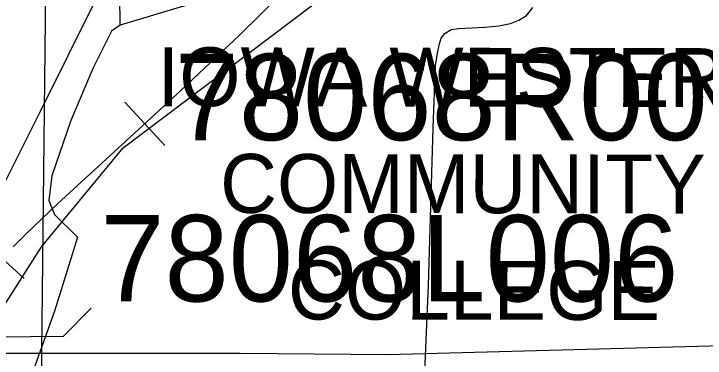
# Model space of a CAD drawing. Extents: x -132.8 to -73.3, y -60 to -26.
# Drawn here: x -119.898 to -119.017, y -48.069 to -47.631 of the extents above; entities that cross this region are included whole.
import ezdxf

# ---------------------------------------------------------------- set-up
doc = ezdxf.new("R2010")
doc.units = 0
for name, color, linetype in [('tdCoCityStreetMajor', 7, 'Continuous'), ('tdCoCityStreetMinor', 7, 'Continuous'), ('tdCoHydroRiver', 7, 'Continuous'), ('tdCoInstTxt', 7, 'Continuous'), ('tdCoPriDiv', 7, 'Continuous'), ('tdCoRRCL', 7, 'Continuous'), ('tdCoSectLine', 7, 'Continuous'), ('tdCoStrucDivPri', 7, 'Continuous'), ('tdCoStrucPriMaintName', 7, 'Continuous')]:
    doc.layers.add(name, color=color, linetype=linetype)

msp = doc.modelspace()

# ---------------------------------------------------------------- linework, layer by layer
at = {"layer": 'tdCoCityStreetMajor'}
msp.add_lwpolyline([(-119.9174, -47.86069), (-119.86389, -47.75489), (-119.79286, -47.61186)], dxfattribs=at)
at = {"layer": 'tdCoCityStreetMinor'}
msp.add_lwpolyline([(-119.37442, -48.08677), (-119.36955, -47.97618), (-119.36364, -47.77618), (-119.36068, -47.69677), (-119.35796, -47.68074), (-119.35574, -47.66915), (-119.35328, -47.66175), (-119.34859, -47.65584), (-119.3407, -47.6509), (-119.33133, -47.64967), (-119.29779, -47.6477), (-119.27979, -47.64597), (-119.26524, -47.64301), (-119.25463, -47.63882), (-119.24477, -47.6329), (-119.23663, -47.62254)], dxfattribs=at)
at = {"layer": 'tdCoHydroRiver'}
for points in [[(-119.17977, -47.29833), (-119.2348, -47.34891), (-119.2579, -47.38615), (-119.28466, -47.44222), (-119.30043, -47.50017), (-119.30089, -47.51751), (-119.31585, -47.5455), (-119.33537, -47.56707), (-119.43131, -47.61338), (-119.4646, -47.61879), (-119.51823, -47.61734), (-119.60264, -47.58666), (-119.61683, -47.58628), (-119.64432, -47.61078), (-119.68567, -47.62228), (-119.76205, -47.64545)], [(-119.76205, -47.64545), (-119.76261, -47.60758)], [(-119.76205, -47.64545), (-119.77331, -47.65304), (-119.79666, -47.69974), (-119.8253, -47.7668), (-119.84929, -47.83715), (-119.85329, -47.8686), (-119.84587, -47.88615), (-119.81667, -47.91534), (-119.82357, -47.93724), (-119.84603, -48.00921), (-119.94498, -48.2842), (-119.94822, -48.28727), (-119.96053, -48.33427), (-119.96705, -48.34198)]]:
    msp.add_lwpolyline(points, dxfattribs=at)
at = {"layer": 'tdCoPriDiv'}
msp.add_lwpolyline([(-120.61573, -48.05639), (-120.53523, -48.05674), (-120.45109, -48.06043), (-120.28612, -48.0624), (-120.14217, -48.0621), (-119.91258, -48.06262), (-119.60963, -48.06303), (-119.42124, -48.06473), (-119.01066, -48.05333), (-118.91558, -48.05033)], dxfattribs=at)
at = {"layer": 'tdCoRRCL'}
for p, q in [((-119.75624, -47.74313), (-119.70547, -47.79833)), ((-119.94025, -47.91742), (-119.8845, -47.96759)), ((-119.98769, -48.12372), (-119.86233, -47.9275))]:
    msp.add_line(p, q, dxfattribs=at)
for points in [[(-119.86233, -47.9275), (-119.75834, -47.80157), (-119.3286, -47.47698)], [(-119.89875, -47.92738), (-119.88303, -47.91165), (-119.84187, -47.87285), (-119.74443, -47.78322), (-119.68485, -47.72841), (-119.6104, -47.65803), (-119.5564, -47.60455)], [(-119.5564, -47.60455), (-119.6104, -47.65803), (-119.68485, -47.72841), (-119.74443, -47.78322), (-119.84187, -47.87285), (-119.88303, -47.91165), (-119.89875, -47.92738)]]:
    msp.add_lwpolyline(points, dxfattribs=at)
at = {"layer": 'tdCoSectLine'}
msp.add_lwpolyline([(-119.86522, -48.3731), (-119.86524, -48.36906), (-119.85445, -47.36885)], dxfattribs=at)
at = {"layer": 'tdCoStrucDivPri'}
for p, q in [((-119.83448, -48.0413), (-119.79908, -48.00541)), ((-119.93961, -48.04204), (-119.83448, -48.0413))]:
    msp.add_line(p, q, dxfattribs=at)

# ---------------------------------------------------------------- texts
at = {"layer": 'tdCoInstTxt'}
for s, p in [('IOWA WESTERN', (-119.71485, -47.74843)), ('IOWA WESTERN', (-119.71485, -47.74843)), ('COMMUNITY', (-119.63502, -47.88415)), ('COMMUNITY', (-119.63502, -47.88415)), ('COLLEGE', (-119.5486, -48.01988)), ('COLLEGE', (-119.5486, -48.01988))]:
    msp.add_text(s, height=0.075, rotation=359.90983, dxfattribs=at).set_placement(p)
at = {"layer": 'tdCoStrucPriMaintName'}
for s, p in [('78068R006', (-119.69283, -47.79167)), ('78068R006', (-119.69283, -47.79167)), ('78068R006', (-119.69283, -47.79167)), ('78068L006', (-119.78761, -47.99697)), ('78068L006', (-119.78761, -47.99697)), ('78068L006', (-119.78761, -47.99697))]:
    msp.add_text(s, height=0.11, dxfattribs=at).set_placement(p)

doc.saveas('drawing.dxf')
